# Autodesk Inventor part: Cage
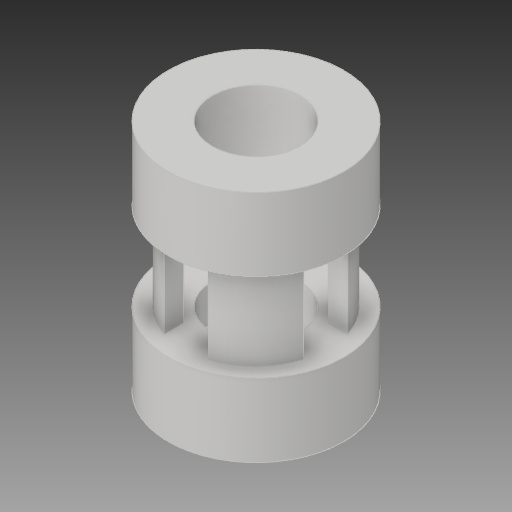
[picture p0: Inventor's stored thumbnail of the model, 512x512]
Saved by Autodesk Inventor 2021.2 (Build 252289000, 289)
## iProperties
Created: 2018-06
Part Number: Cage
Material: Plastique ABS
Document SubType Name: Modeling
Designer: Fabian Perrée
Density: 1.06 g/cm^3
Appearance: Lisse - Blanc
Author: Fabian Perrée
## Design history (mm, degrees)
sketch "Esquisse1"
  geometry: L1 (0, 0)-(0, 16); L2 (3, 16)-(6, 16); L3 (6, 16)-(6, 11); L4 (3, 11)-(3, 16); L5 (6, 5)-(6, 0); L6 (6, 0)-(0, 0); L7 (3, 5)-(3, 2.5); L8 (3, 2.5)-(0, 2.5); L9 (3.75, 11)-(3.75, 5); L10 (5, 11)-(5, 5); L11 (6, 11)-(5, 11); L12 (3.75, 11)-(3, 11); L13 (6, 5)-(5, 5); L14 (3.75, 5)-(3, 5)
  constraints: 28 end point, 8 perpendicular, 4 collinear, 4 horizontal, 4 point on line, 3 parallel, 1 vertical
  dimensions: "d0" = 16 distance of L1.start L1.end; "d2" = 12 diameter of L3 L1; "d3" = 6 diameter of L4 L1; "d4" = 5 distance of L2.end L3.end; "d7" = 13.5 distance between parallel lines of L2 L8; "d8" = 7.5 diameter of L9 L1; "d9" = 10 diameter of L10 L1; "d10" = 6 distance between parallel lines of L11 L13
revolve "Révolution1" sketch "Esquisse1" stored, may be unused: angle "d11" = 90 deg
sketch "Esquisse2"
  geometry: L1 (-5.809, -1.5)-(-2.598, -1.5); L2 (-2.598, -1.5)-(-2.598, 1.5); L3 (-2.598, 1.5)-(-5.809, 1.5); L4 (-5.809, 1.5)-(-5.809, -1.5); L5 (-6, 0)-(0, 0); A1 r 6 centre (0, 0) between (-5.809, -1.5) and (-6, 0) reference; 1 further point
  constraints: 10 end point, 2 parallel, 2 perpendicular, 2 point on circle, 1 horizontal, 3 other
  dimensions: "d12" = 3 distance of L3.end L1.start
extrude "Extrusion1" cut sketch "Esquisse2" stored distance "d13" = 10; taper "d14" = 0 deg
pattern_circular "Réseau circulaire1" dims angle "d16" = 360 deg
feature "Scission1"
node "Solide1"
other parameters: "d6" = 6
